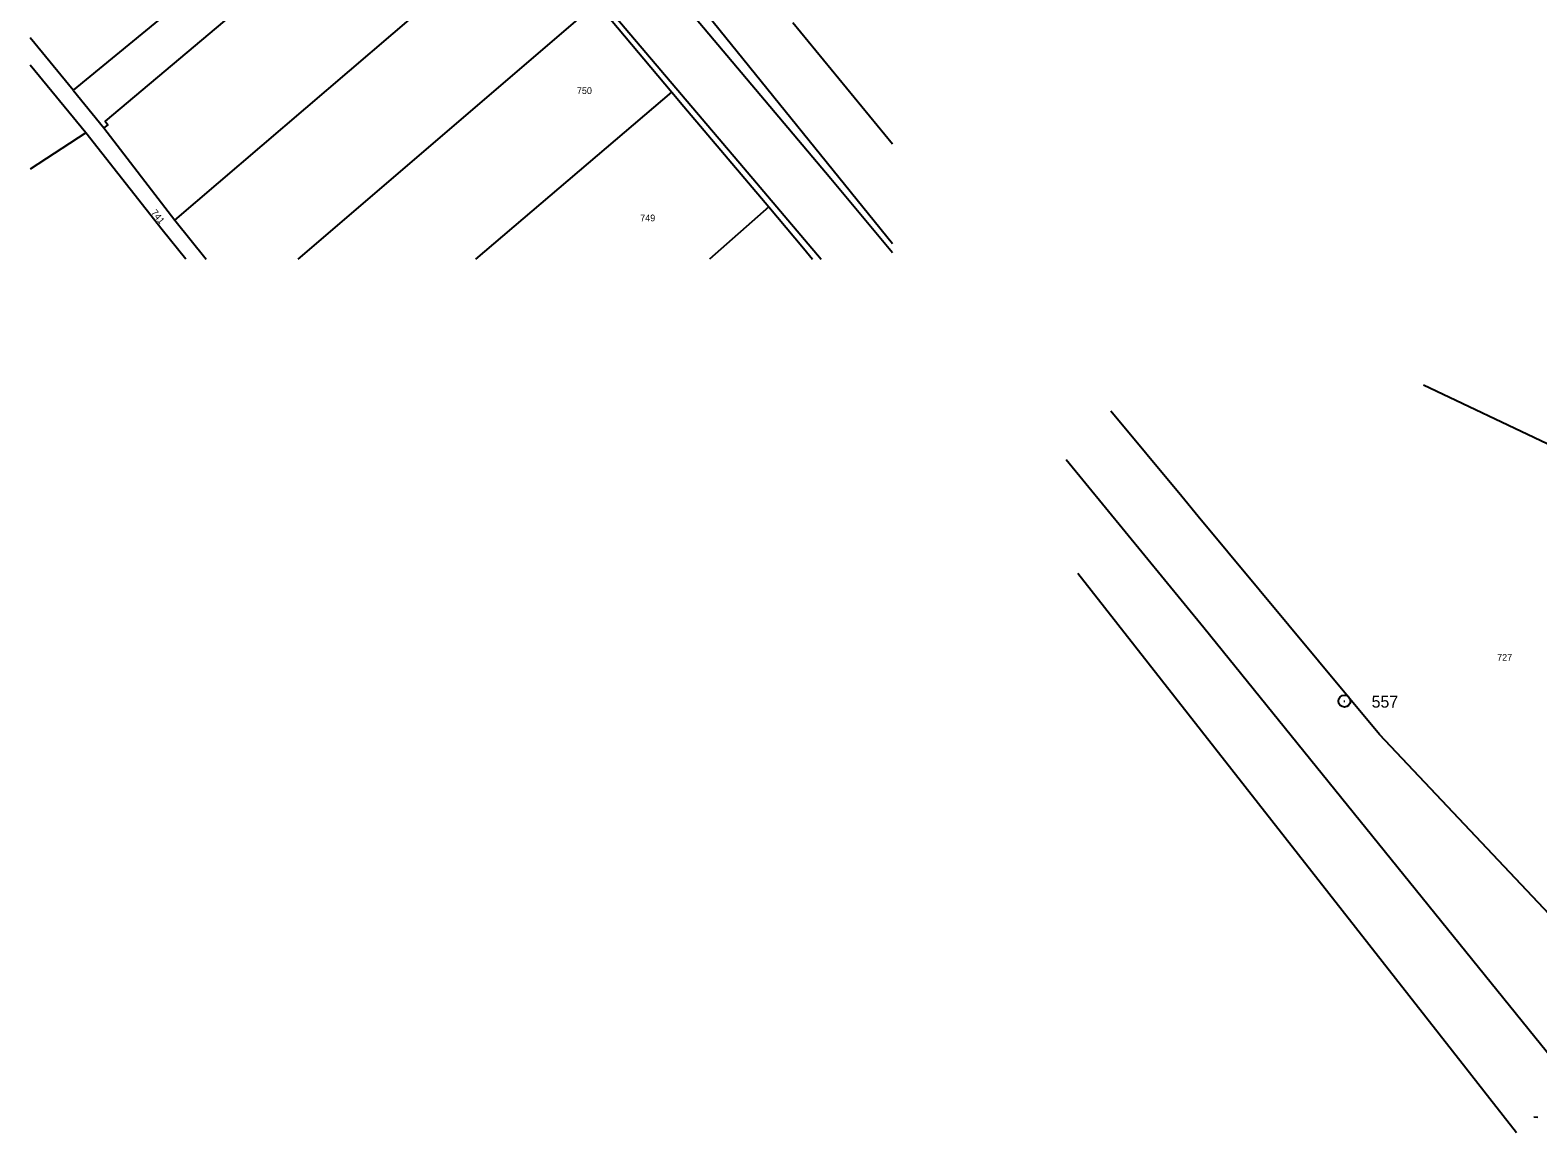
# Model space of a CAD drawing. Extents: x -504997 to -503568, y -1079870 to -1078007.
# Drawn here: x -504599.7 to -504219.1, y -1079146.8 to -1078870.4 of the extents above; entities that cross this region are included whole.
import ezdxf

# ---------------------------------------------------------------- set-up
doc = ezdxf.new("R2010")
doc.units = 0
for name, color, linetype in [('Hranice parcel', 7, 'Continuous'), ('Parcelní čísla', 7, 'Continuous'), ('Vnitřní kresba', 7, 'Continuous'), ('Vrstva 30', 7, 'Continuous'), ('Vrstva 31', 7, 'Continuous'), ('Vrstva 32', 7, 'Continuous'), ('Vrstva 54', 7, 'Continuous')]:
    doc.layers.add(name, color=color, linetype=linetype)

msp = doc.modelspace()

# ---------------------------------------------------------------- linework, layer by layer
at = {"layer": 'Hranice parcel'}
for p, q in [((-504563.23, -1078918.36), (-504475.16, -1078843.09)), ((-504456.8, -1078863.69), (-504532.18, -1078928.23)), ((-504407.21, -1078868.45), (-504382.03, -1078899.14)), ((-504588.84, -1078885.56), (-504599.72, -1078872.39)), ((-504588.84, -1078885.56), (-504581.08, -1078895.08)), ((-504487.22, -1078928.23), (-504437.71, -1078886.11)), ((-504581.08, -1078895.08), (-504563.23, -1078918.36)), ((-504563.23, -1078918.36), (-504555.31, -1078928.23)), ((-504413.27, -1078915.05), (-504428.26, -1078928.23)), ((-504248.02, -1078959.95), (-504216.74, -1078974.75)), ((-504237.3, -1079132.48), (-504335.24, -1079007.61))]:
    msp.add_line(p, q, dxfattribs=at)
for points in [[(-504597.09, -1078667.4), (-504514.19, -1078765.94), (-504428.7, -1078866.55), (-504382.03, -1078924.33)], [(-504382.03, -1078926.66), (-504397.6, -1078907.92), (-504520.79, -1078761.79), (-504523.08, -1078763.96), (-504532.75, -1078752.34), (-504530.29, -1078750.16), (-504595.19, -1078673.8)], [(-504510.65, -1078797.8), (-504419.66, -1078905.09), (-504400.02, -1078928.23)], [(-504501.14, -1078813.49), (-504535, -1078841.31), (-504588.84, -1078885.56)], [(-504494.6, -1078820.86), (-504580.77, -1078893.36), (-504580.15, -1078894.29), (-504581.08, -1078895.08)], [(-504456.8, -1078863.69), (-504453.26, -1078867.66), (-504437.71, -1078886.11)], [(-504585.64, -1078896.32), (-504599.72, -1078879.24)], [(-504437.71, -1078886.11), (-504434.71, -1078889.67), (-504413.27, -1078915.05)], [(-504585.64, -1078896.32), (-504599.72, -1078905.56)], [(-504560.44, -1078928.23), (-504566.37, -1078920.84), (-504585.64, -1078896.32)], [(-504413.27, -1078915.05), (-504404.47, -1078925.46), (-504402.2, -1078928.23)], [(-504191.97, -1079119.35), (-504259.1, -1079048.24), (-504304.84, -1078993.19), (-504309, -1078988.18), (-504326.93, -1078966.59)], [(-504048.32, -1079336.41), (-504164.13, -1079193.65), (-504189.98, -1079161.66), (-504303.4, -1079021.3), (-504338.19, -1078978.95)], [(-504224.49, -1079148.81), (-504231.2, -1079140.26), (-504237.3, -1079132.48)]]:
    msp.add_lwpolyline(points, dxfattribs=at)
at = {"layer": 'Vnitřní kresba'}
msp.add_line((-504220.12, -1079144.83), (-504219.12, -1079144.85), dxfattribs=at)
at = {"layer": 'Vrstva 30'}
msp.add_line((-504268.06, -1079039.84), (-504267.86, -1079039.84), dxfattribs=at)
msp.add_circle((-504267.96, -1079039.84), 1.51, dxfattribs=at)
at = {"layer": 'Vrstva 31'}
msp.add_line((-504267.96, -1079039.84), (-504267.96, -1079039.84), dxfattribs=at)
at = {"layer": 'Vrstva 54'}
for points in [[(-503895.86, -1079458.07), (-503942.64, -1079419.51), (-503946.4, -1079416.88), (-503945.84, -1079414.89), (-503977.25, -1079388.9), (-504014.44, -1079358.14), (-504038.99, -1079330.47), (-504044.97, -1079331.7), (-504048.32, -1079336.41), (-504164.13, -1079193.65), (-504189.98, -1079161.66), (-504303.4, -1079021.3)], [(-504259.1, -1079048.24), (-504191.97, -1079119.35), (-504187.04, -1079125.02), (-504168.33, -1079151.66), (-504150.39, -1079177.22), (-504141.49, -1079189.89), (-504109.47, -1079227.67), (-504070.38, -1079273.8), (-504043.38, -1079305.66), (-504041.43, -1079307.47), (-504008.27, -1079338.19), (-503988.82, -1079356.2), (-503938.33, -1079402.97), (-503888.76, -1079443.21)]]:
    msp.add_lwpolyline(points, dxfattribs=at)

# ---------------------------------------------------------------- texts
at = {"layer": 'Parcelní čísla'}
for s, p in [('750', (-504461.7, -1078886.54)), ('749', (-504445.72, -1078918.68)), ('727', (-504229.4, -1079029.66))]:
    msp.add_text(s, height=1.7, dxfattribs=at).set_placement(p)
msp.add_text('741', height=1.7, rotation=308, dxfattribs=at).set_placement((-504569.28, -1078916.53))
at = {"layer": 'Vrstva 32'}
msp.add_text('557', height=3, dxfattribs=at).set_placement((-504261.08, -1079041.48))

doc.saveas('drawing.dxf')
